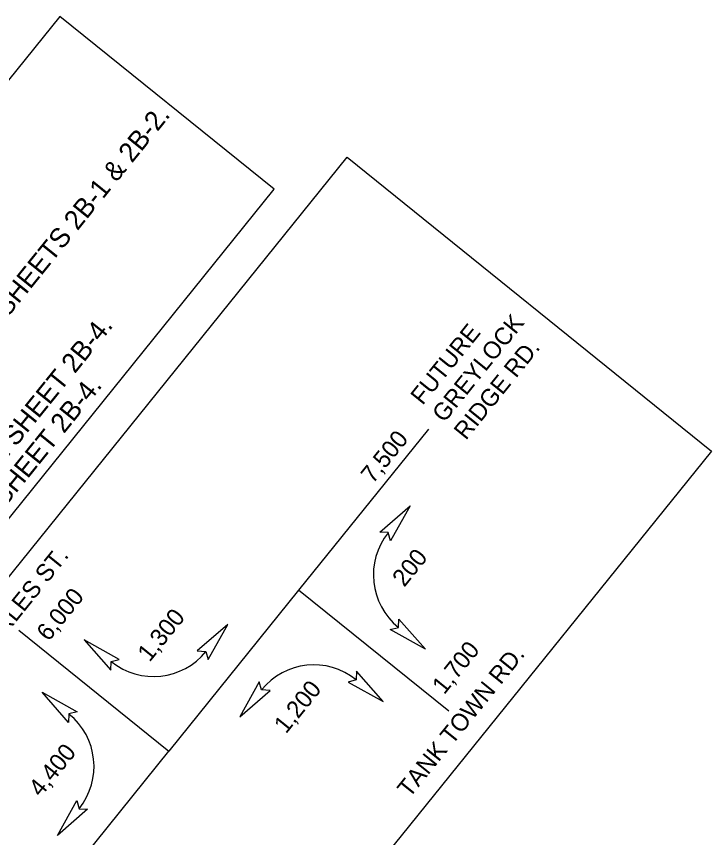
# Model space of a CAD drawing. Extents: x 1487875 to 1489967, y 498345 to 500495.
# Drawn here: x 1489766.6 to 1489967.3, y 499770.6 to 500007.7 of the extents above; entities that cross this region are included whole.
import ezdxf

# ---------------------------------------------------------------- set-up
doc = ezdxf.new("R2010")
doc.units = 0
for name, color, linetype in [('Exist Utilities Gas UG Line SUE LOS B', 7, 'Continuous'), ('Exist Utilities Telephone UG FO SUE LOS B', 7, 'Continuous'), ('Exist Utilities Water Meter CELL', 7, 'Continuous')]:
    doc.layers.add(name, color=color, linetype=linetype)

msp = doc.modelspace()

# ---------------------------------------------------------------- linework, layer by layer
at = {"layer": 'Exist Utilities Telephone UG FO SUE LOS B'}
for p, q in [((1489885.56, 499888.52), (1489848.05, 499842.02)), ((1489848.05, 499842.02), (1489810.55, 499795.51)), ((1489891.38, 499807.08), (1489848.05, 499842.02)), ((1489767.23, 499830.45), (1489810.55, 499795.51)), ((1489773.05, 499749.01), (1489810.55, 499795.51))]:
    msp.add_line(p, q, dxfattribs=at)
for points in [[(1489871.53, 499858.77), (1489880.21, 499866.4), (1489874.59, 499856.21), (1489873.93, 499858.62)], [(1489877.01, 499833.68), (1489884.64, 499825), (1489874.46, 499830.61), (1489876.86, 499831.28)], [(1489821.95, 499822.01), (1489827.57, 499832.1), (1489818.8, 499824.46), (1489821.29, 499824.32)], [(1489796.27, 499822.04), (1489786.17, 499827.67), (1489793.81, 499818.9), (1489793.95, 499821.39)], [(1489862.34, 499815.49), (1489872.44, 499809.86), (1489864.79, 499818.63), (1489864.65, 499816.14)], [(1489836.66, 499815.53), (1489831.04, 499805.43), (1489839.8, 499813.07), (1489837.31, 499813.21)], [(1489781.6, 499803.85), (1489773.96, 499812.53), (1489784.15, 499806.92), (1489781.74, 499806.26)], [(1489787.08, 499778.77), (1489778.4, 499771.13), (1489784.01, 499781.32), (1489784.67, 499778.91)]]:
    msp.add_lwpolyline(points, close=True, dxfattribs=at)
for centre, start, end in [((1489889.07, 499846.41), 141.1156, 231.1156), ((1489806.16, 499836.53), 231.1156, 321.1156), ((1489852.45, 499801), 51.1156, 141.1156), ((1489769.54, 499791.12), 321.1156, 51.1156)]:
    msp.add_arc(centre, 19.44, start, end, dxfattribs=at)
at = {"layer": 'Exist Utilities Water Meter CELL'}
for points in [[(1489692.75, 499773.9), (1489841.02, 499957.76), (1489779.13, 500007.67), (1489630.85, 499823.81)], [(1489692.49, 499756.77), (1489862.05, 499967.03), (1489967.26, 499882.18), (1489797.7, 499671.92)]]:
    msp.add_lwpolyline(points, close=True, dxfattribs=at)

# ---------------------------------------------------------------- texts
at = {"layer": 'Exist Utilities Gas UG Line SUE LOS B'}
for s, p in [('FOR -SIDEPATH- ALIGNMENT DETAIL SEE SHEETS 2B-1 & 2B-2.', (1489667.17, 499800.52)), ('FOR INTERSECTION DETAILS SEE SHEET 2B-4.', (1489686.88, 499784.63)), ('FOR -L- MEDIAN DETAILS SEE SHEET 2B-4.', (1489693.44, 499779.34))]:
    msp.add_text(s, height=5.625, rotation=51.1156, dxfattribs=at).set_placement(p)
at = {"layer": 'Exist Utilities Telephone UG FO SUE LOS B'}
for s, p in [('GREYLOCK', (1489890.08, 499890.15)), ('FUTURE', (1489883.83, 499895.2)), ('RIDGE RD.', (1489896.34, 499885.11)), ('7,500', (1489869.48, 499872.52)), ('E. CHARLES ST.', (1489749.3, 499811.46)), ('200', (1489878.55, 499842.68)), ('6,000', (1489775.86, 499827.01)), ('1,300', (1489805.02, 499821.05)), ('1,700', (1489890.07, 499811.65)), ('TANK TOWN RD.', (1489880.04, 499781.81)), ('1,200', (1489844.4, 499800.33)), ('4,400', (1489773.58, 499782.06))]:
    msp.add_text(s, height=5, rotation=51.1156, dxfattribs=at).set_placement(p)

doc.saveas('drawing.dxf')
